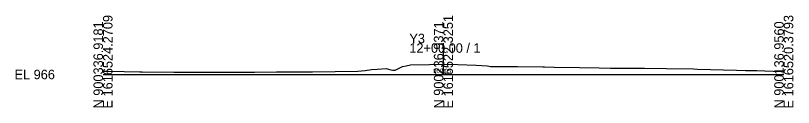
# Model space of a CAD drawing. Extents: x -26 to 203, y -10 to 2017.
# Drawn here: x -25.7 to 202.8, y 1990.3 to 2017.3 of the extents above; entities that cross this region are included whole.
import ezdxf

# ---------------------------------------------------------------- set-up
doc = ezdxf.new("R2010")
doc.units = 0
for name, color, linetype in [('Exist Cross Section Cell', 7, 'Continuous'), ('Exist XS Center Line Elevation Label', 7, 'Continuous'), ('Exist XS Ground Line', 7, 'Continuous')]:
    doc.layers.add(name, color=color, linetype=linetype)

msp = doc.modelspace()

# ---------------------------------------------------------------- linework, layer by layer
at = {"layer": 'Exist Cross Section Cell'}
for p, q in [((100, 2000), (100, 2009.17)), ((0, 2000), (100, 2000)), ((100, 2000), (200, 2000))]:
    msp.add_line(p, q, dxfattribs=at)
at = {"layer": 'Exist XS Ground Line'}
for p, q in [((86.43, 2001.56), (87.99, 2002.37)), ((87.99, 2002.37), (89.02, 2002.56)), ((89.02, 2002.56), (90.35, 2002.83)), ((90.35, 2002.83), (95.89, 2002.95)), ((95.89, 2002.95), (100.22, 2003.06)), ((100.22, 2003.06), (104.23, 2002.91)), ((104.23, 2002.91), (109.66, 2002.74)), ((109.66, 2002.74), (112.83, 2002.52)), ((112.83, 2002.52), (113.85, 2002.39)), ((113.85, 2002.39), (115.5, 2002.38)), ((115.5, 2002.38), (118.93, 2002.33)), ((118.93, 2002.33), (121.82, 2002.3)), ((121.82, 2002.3), (129.19, 2002.2)), ((129.19, 2002.2), (129.67, 2002.2)), ((129.67, 2002.2), (132.54, 2002.16)), ((132.54, 2002.16), (139.94, 2002.04)), ((139.94, 2002.04), (145.76, 2001.91)), ((0, 2000.98), (0.83, 2000.97)), ((0.83, 2000.97), (1.66, 2000.95)), ((1.66, 2000.95), (10.83, 2000.81)), ((10.83, 2000.81), (11.48, 2000.8)), ((11.48, 2000.8), (20.84, 2000.65)), ((20.84, 2000.65), (21.29, 2000.65)), ((21.29, 2000.65), (31.1, 2000.66)), ((31.1, 2000.66), (40.91, 2000.71)), ((40.91, 2000.71), (44.48, 2000.72)), ((44.48, 2000.72), (50.97, 2000.74)), ((50.97, 2000.74), (60.84, 2000.78)), ((60.84, 2000.78), (61.5, 2000.79)), ((61.5, 2000.79), (74.87, 2000.93)), ((74.87, 2000.93), (77.04, 2001.2)), ((77.04, 2001.2), (78.89, 2001.47)), ((78.89, 2001.47), (80.55, 2001.59)), ((80.55, 2001.59), (83.14, 2001.78)), ((83.14, 2001.78), (84.57, 2001.4)), ((84.57, 2001.4), (85.1, 2001.25)), ((85.1, 2001.25), (85.85, 2001.25)), ((85.85, 2001.25), (86.43, 2001.56)), ((145.76, 2001.91), (149.05, 2001.88)), ((149.05, 2001.88), (155.27, 2001.88)), ((155.27, 2001.88), (158.31, 2001.89)), ((158.31, 2001.89), (158.66, 2001.88)), ((158.66, 2001.88), (159.05, 2001.88)), ((159.05, 2001.88), (165.51, 2001.79)), ((165.51, 2001.79), (173.44, 2001.61)), ((173.44, 2001.61), (174.68, 2001.56)), ((174.68, 2001.56), (186.13, 2001.27)), ((186.13, 2001.27), (188.78, 2001.18)), ((188.78, 2001.18), (192.13, 2001.13)), ((192.13, 2001.13), (199.22, 2000.89)), ((199.22, 2000.89), (199.53, 2000.86)), ((199.53, 2000.86), (200, 2000.86))]:
    msp.add_line(p, q, dxfattribs=at)

# ---------------------------------------------------------------- texts
at = {"layer": 'Exist Cross Section Cell'}
for s, p in [('E 1616524.2709', (2.8, 1990)), ('E 1616522.3251', (102.8, 1990)), ('E 1616520.3793', (202.8, 1990)), ('N 900336.9181', (0, 1990)), ('N 900236.9371', (100, 1990)), ('N 900136.9560', (200, 1990))]:
    msp.add_text(s, height=2.8, rotation=90, dxfattribs=at).set_placement(p)
for s, p in [('Y3', (90, 2009.17)), ('12+00.00 / 1', (90, 2006.37)), ('EL 966', (-26, 1998.6))]:
    msp.add_text(s, height=2.8, dxfattribs=at).set_placement(p)
at = {"layer": 'Exist XS Center Line Elevation Label'}
msp.add_text('969.05', height=1.25, dxfattribs=at).set_placement((97.02, 2000.43))

doc.saveas('drawing.dxf')
